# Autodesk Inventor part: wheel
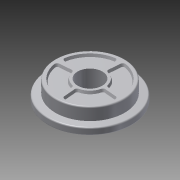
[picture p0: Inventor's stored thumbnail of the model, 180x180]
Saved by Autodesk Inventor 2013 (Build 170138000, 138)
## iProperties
Created: 2009-11
Part Number: wheel
Document SubType Name: Modeling
Designer: pokornp
Density: 1 g/cm^3
Material: Generic
Author: pokornp
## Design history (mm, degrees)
sketch "Sketch2"
  geometry: L1 (50, 0)-(50, 80); L2 (50, 80)-(140, 80); L3 (140, 80)-(140, 30); L4 (170, 0)-(50, 0); L5 (0, -16)-(0, 96) reference; L6 (140, 30)-(170, 27.375); L7 (170, 27.375)-(170, 0); 1 further point
  constraints: 12 end point, 3 parallel, 1 horizontal alignment, 1 perpendicular, 1 vertical
  dimensions: "d2" = 80 distance of L1.start L1.end; "d3" = 50 distance from line of point (0, 0) L1; "d4" = 170 distance of point (0, 0) L4.start; "d8" = 5 deg angle of L4 L6; "d9" = 50 distance of L2.end L3.end; "d10" = 90 distance of L1.end L2.end
revolve "Revolution1" sketch "Sketch2" stored, may be unused: angle "d7" = 90 deg
fillet "Fillet1" dims "d11" = 5
sketch "Sketch3"
  geometry: L1 (-69.018, -6.038)-(-114.128, -9.985); L2 (-238, 0)-(238, 0) reference; L3 (0, -238)-(0, 238) reference; L4 (-6.038, -69.018)-(-9.985, -114.128); C1 r 135 at (0, 0) reference; A1 r 125 centre (0, 0) between (-123.105, -21.681) and (-21.681, -123.105); A2 r 60 centre (0, 0) between (-58.412, -13.715) and (-13.715, -58.412); A3 r 10 centre (-19.947, -113.257) between (-21.681, -123.105) and (-9.985, -114.128); A4 r 10 centre (-113.257, -19.947) between (-114.128, -9.985) and (-123.105, -21.681); A5 r 10 centre (-68.147, -16) between (-58.412, -13.715) and (-69.018, -6.038); A6 r 10 centre (-16, -68.147) between (-6.038, -69.018) and (-13.715, -58.412); 4 further points
  constraints: 16 point on circle, 8 tangent, 6 centre point, 4 end point, 4 point on line, 3 equal radius, 2 coincident
  dimensions: "d12" = 120 diameter of A2; "d13" = 250 diameter of A1; "d14" = 5 deg angle of L1 L2; "d16" = 10 radius of A3
extrude "Extrusion1" cut sketch "Sketch3" distance "d17" = 10; taper "d18" = -20 deg
pattern_circular "Circular Pattern1" dims angle "d20" = 360 deg
workplane "Work Plane1"
body "Solid1"
other parameters: "d15" = 5 deg
